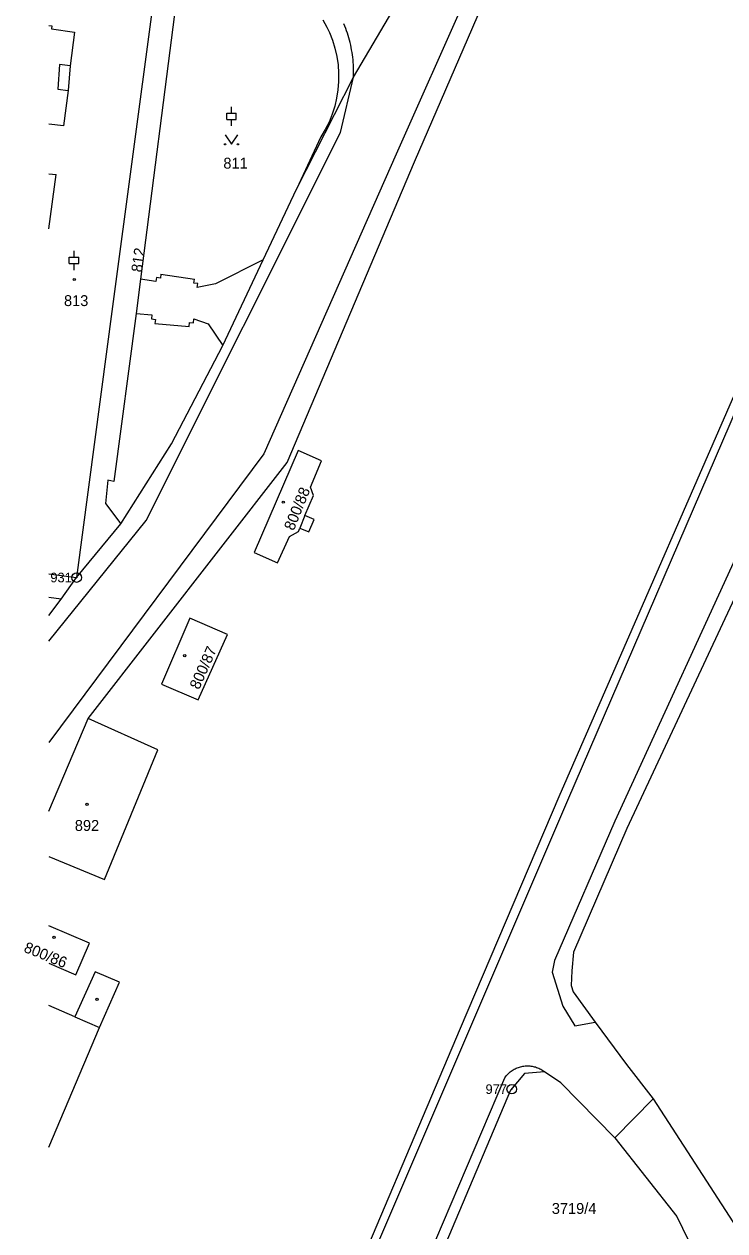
# Model space of a CAD drawing. Extents: x -747779 to -747197, y -965543 to -964919.
# Drawn here: x -747779.4 to -747670.1, y -965237.8 to -965049.6 of the extents above; entities that cross this region are included whole.
import ezdxf

# ---------------------------------------------------------------- set-up
doc = ezdxf.new("R2010")
doc.units = 0
for name, color, linetype in [('Hranice parcel', 7, 'Continuous'), ('Parcelní čísla', 7, 'Continuous'), ('Vnitřní kresba', 7, 'Continuous'), ('Značky bodu BP', 7, 'Continuous'), ('Značky budov', 7, 'Continuous'), ('Značky kultur', 7, 'Continuous')]:
    doc.layers.add(name, color=color, linetype=linetype)

msp = doc.modelspace()

# ---------------------------------------------------------------- linework, layer by layer
at = {"layer": 'Hranice parcel'}
for p, q in [((-747733.06, -965067.14), (-747736.89, -965075.33)), ((-747771.17, -965135.89), (-747764.28, -965127.51)), ((-747775.53, -965172.32), (-747769.38, -965157.87)), ((-747681.26, -965217.18), (-747687.21, -965223.29)), ((-747681.26, -965217.18), (-747664.09, -965243.73))]:
    msp.add_line(p, q, dxfattribs=at)
for points in [[(-747736.89, -965075.33), (-747728, -965057.84), (-747715.19, -965036.1), (-747687.81, -965009.8), (-747684.76, -965006.87), (-747683.74, -965004.84), (-747681.46, -965000.29)], [(-747769.38, -965157.87), (-747738.35, -965117.94), (-747718.46, -965071.07), (-747704.48, -965038.72), (-747704.11, -965038.88), (-747702.83, -965035.74), (-747698.69, -965025.95), (-747696.3, -965025.06), (-747693.83, -965026.45), (-747689.32, -965018.57), (-747684.62, -965015.84), (-747684.96, -965015.71), (-747684.72, -965015.07), (-747684.2, -965013.72), (-747680.21, -965004.33), (-747679.47, -965002.51), (-747679.51, -965002.12)], [(-747755.52, -965039.54), (-747756.37, -965045.62), (-747755.64, -965045.97), (-747761.21, -965089.37), (-747761.89, -965094.71), (-747765.38, -965120.93), (-747766.32, -965120.72), (-747766.67, -965124.36), (-747764.28, -965127.51)], [(-747759.34, -965046.86), (-747765.55, -965093.63), (-747771.17, -965135.89)], [(-747732.78, -965048.89), (-747732.14, -965050.03), (-747731.75, -965050.86), (-747731.27, -965052.08), (-747730.88, -965053.33), (-747730.58, -965054.6), (-747730.39, -965055.9), (-747730.3, -965057.2), (-747730.3, -965058.51), (-747730.41, -965059.82), (-747730.61, -965061.11), (-747730.91, -965062.39), (-747731.31, -965063.63), (-747731.8, -965064.84), (-747732.39, -965066.02), (-747733.06, -965067.14)], [(-747656.73, -965070.94), (-747661.79, -965091.8), (-747695.94, -965170.11), (-747711.36, -965206.23), (-747731.59, -965253.94)], [(-747764.28, -965127.51), (-747756.35, -965115.01), (-747748.36, -965099.71), (-747742.09, -965086.33), (-747736.89, -965075.33)], [(-747638.82, -965075.9), (-747639.42, -965076.84), (-747685.36, -965175.02), (-747693.65, -965194.31), (-747693.94, -965197.22), (-747694.04, -965199.52), (-747693.72, -965200.53), (-747690.27, -965205.24), (-747685.4, -965211.83), (-747681.26, -965217.18)], [(-747737.97, -965129.47), (-747736.58, -965128.7), (-747736.36, -965128.18), (-747734.96, -965128.78), (-747734.1, -965126.85), (-747735.55, -965126.22), (-747734.24, -965123.07), (-747734.71, -965121.78), (-747732.96, -965117.67), (-747736.63, -965116.06), (-747743.49, -965132), (-747739.82, -965133.61), (-747737.97, -965129.47)], [(-747775.53, -965135.31), (-747771.17, -965135.89)], [(-747775.53, -965141.81), (-747773.59, -965139.28), (-747771.17, -965135.89)], [(-747747.66, -965144.77), (-747753.49, -965142.24), (-747757.94, -965152.5), (-747752.19, -965154.98), (-747747.66, -965144.77)], [(-747775.53, -965179.42), (-747766.8, -965183), (-747758.5, -965162.75), (-747769.38, -965157.87)], [(-747775.53, -965196.03), (-747771.29, -965197.86), (-747769.14, -965192.93), (-747775.53, -965190.21)], [(-747775.53, -965224.76), (-747767.62, -965206.07), (-747764.49, -965199.02), (-747768.28, -965197.41), (-747771.44, -965204.42), (-747775.53, -965202.65)], [(-747687.21, -965223.29), (-747695.62, -965214.69), (-747698.17, -965212.99), (-747701.29, -965213.25), (-747703.51, -965215.83), (-747730.8, -965280.44), (-747731.85, -965282.88)], [(-747687.21, -965223.29), (-747677.55, -965235.57), (-747674.82, -965241.09), (-747670.12, -965258.53)]]:
    msp.add_lwpolyline(points, dxfattribs=at)
at = {"layer": 'Vnitřní kresba'}
for p, q in [((-747705.09, -965033.38), (-747721.35, -965069.83)), ((-747775.53, -965049.78), (-747775.04, -965049.86)), ((-747775.04, -965049.86), (-747775.11, -965050.3)), ((-747775.11, -965050.3), (-747771.49, -965050.84)), ((-747771.49, -965050.84), (-747772.18, -965056.08)), ((-747773.82, -965055.87), (-747774.12, -965059.7)), ((-747772.18, -965056.08), (-747773.82, -965055.87)), ((-747772.18, -965056.08), (-747772.51, -965059.91)), ((-747729.99, -965066.46), (-747728, -965057.84)), ((-747774.12, -965059.7), (-747772.51, -965059.91)), ((-747772.51, -965059.91), (-747773.23, -965065.46)), ((-747773.23, -965065.46), (-747775.53, -965065.18)), ((-747760.34, -965126.97), (-747729.99, -965066.46)), ((-747721.35, -965069.83), (-747741.97, -965116.6)), ((-747775.53, -965072.92), (-747774.38, -965073.05)), ((-747775.53, -965081.5), (-747774.38, -965073.05)), ((-747643.7, -965078.9), (-747687.21, -965173.91)), ((-747742.09, -965086.33), (-747749.51, -965090.09)), ((-747758.82, -965089.72), (-747761.21, -965089.37)), ((-747758.73, -965089.11), (-747758.82, -965089.72)), ((-747758.11, -965089.2), (-747758.73, -965089.11)), ((-747758.02, -965088.58), (-747758.11, -965089.2)), ((-747758.02, -965088.58), (-747752.79, -965089.34)), ((-747752.88, -965089.96), (-747752.79, -965089.34)), ((-747752.26, -965090.05), (-747752.88, -965089.96)), ((-747752.35, -965090.66), (-747752.26, -965090.05)), ((-747749.51, -965090.09), (-747752.35, -965090.66)), ((-747660.59, -965091.74), (-747694.6, -965170.66)), ((-747761.89, -965094.71), (-747759.46, -965094.93)), ((-747759.46, -965094.93), (-747759.51, -965095.56)), ((-747759.51, -965095.56), (-747758.89, -965095.62)), ((-747758.89, -965095.62), (-747758.95, -965096.24)), ((-747758.95, -965096.24), (-747753.63, -965096.73)), ((-747753.63, -965096.73), (-747753.57, -965096.11)), ((-747753.57, -965096.11), (-747752.95, -965096.17)), ((-747752.95, -965096.17), (-747752.89, -965095.54)), ((-747752.89, -965095.54), (-747750.66, -965096.31)), ((-747750.66, -965096.31), (-747748.36, -965099.71)), ((-747741.97, -965116.6), (-747775.53, -965161.63)), ((-747775.53, -965145.83), (-747760.34, -965126.97)), ((-747735.55, -965126.22), (-747736.36, -965128.18)), ((-747773.59, -965139.28), (-747775.53, -965139)), ((-747694.6, -965170.66), (-747730.5, -965254.41)), ((-747687.21, -965173.91), (-747696.62, -965195.61)), ((-747696.62, -965195.61), (-747697, -965197.45)), ((-747697, -965197.45), (-747695.33, -965202.76)), ((-747771.44, -965204.42), (-747767.62, -965206.07)), ((-747695.33, -965202.76), (-747693.45, -965205.83)), ((-747693.45, -965205.83), (-747690.27, -965205.24)), ((-747731.13, -965276.6), (-747704.39, -965213.92))]:
    msp.add_line(p, q, dxfattribs=at)
for points in [[(-747728, -965057.84), (-747727.98, -965057.45), (-747727.98, -965057.07), (-747727.98, -965056.68), (-747727.99, -965056.29), (-747728, -965055.9), (-747728.03, -965055.52), (-747728.06, -965055.13), (-747728.1, -965054.75), (-747728.15, -965054.36), (-747728.2, -965053.98), (-747728.27, -965053.6), (-747728.34, -965053.22), (-747728.42, -965052.84), (-747728.51, -965052.46), (-747728.6, -965052.08), (-747728.71, -965051.71), (-747728.82, -965051.34), (-747728.94, -965050.97), (-747729.06, -965050.6), (-747729.19, -965050.24), (-747729.33, -965049.88), (-747729.48, -965049.52)], [(-747704.39, -965213.92), (-747704.29, -965213.77), (-747704.17, -965213.63), (-747704.06, -965213.49), (-747703.93, -965213.36), (-747703.81, -965213.23), (-747703.67, -965213.11), (-747703.53, -965212.99), (-747703.39, -965212.88), (-747703.24, -965212.78), (-747703.09, -965212.68), (-747702.93, -965212.59), (-747702.77, -965212.51), (-747702.61, -965212.43), (-747702.44, -965212.36), (-747702.27, -965212.29), (-747702.1, -965212.24), (-747701.93, -965212.19), (-747701.75, -965212.15), (-747701.57, -965212.11), (-747701.39, -965212.08), (-747701.21, -965212.07), (-747701.03, -965212.05), (-747700.85, -965212.05), (-747700.67, -965212.05), (-747700.49, -965212.06), (-747700.31, -965212.08), (-747700.13, -965212.11), (-747699.95, -965212.14), (-747699.78, -965212.19), (-747699.6, -965212.23), (-747699.43, -965212.29), (-747699.26, -965212.35), (-747699.09, -965212.43), (-747698.93, -965212.5), (-747698.77, -965212.59), (-747698.61, -965212.68), (-747698.46, -965212.78), (-747698.31, -965212.88), (-747698.17, -965212.99)]]:
    msp.add_lwpolyline(points, dxfattribs=at)
at = {"layer": 'Značky bodu BP'}
for centre, radius in [((-747771.17, -965135.89), 0.75), ((-747771.17, -965135.89), 0.03), ((-747703.29, -965215.69), 0.75), ((-747703.29, -965215.69), 0.03)]:
    msp.add_circle(centre, radius, dxfattribs=at)
at = {"layer": 'Značky budov'}
for centre in [(-747771.53, -965089.4), (-747738.93, -965124.13), (-747754.3, -965148.07), (-747769.55, -965171.26), (-747774.69, -965192), (-747767.99, -965201.67)]:
    msp.add_circle(centre, 0.175, dxfattribs=at)
at = {"layer": 'Značky kultur'}
for p, q in [((-747747.01, -965063.45), (-747747.01, -965062.45)), ((-747747.76, -965063.45), (-747746.26, -965063.45)), ((-747747.76, -965064.45), (-747747.76, -965063.45)), ((-747747.76, -965064.45), (-747746.26, -965064.45)), ((-747747.01, -965065.45), (-747747.01, -965064.45)), ((-747746.26, -965064.45), (-747746.26, -965063.45)), ((-747772.33, -965085.93), (-747770.83, -965085.93)), ((-747772.33, -965086.93), (-747772.33, -965085.93)), ((-747771.58, -965085.93), (-747771.58, -965084.93)), ((-747770.83, -965086.93), (-747770.83, -965085.93)), ((-747772.33, -965086.93), (-747770.83, -965086.93)), ((-747771.58, -965087.93), (-747771.58, -965086.93))]:
    msp.add_line(p, q, dxfattribs=at)
msp.add_lwpolyline([(-747748.01, -965066.82), (-747747.01, -965068.32), (-747746.01, -965066.82)], dxfattribs=at)
for centre in [(-747748.01, -965068.32), (-747746.01, -965068.32)]:
    msp.add_circle(centre, 0.1, dxfattribs=at)

# ---------------------------------------------------------------- texts
at = {"layer": 'Parcelní čísla'}
for s, p in [('811', (-747748.28, -965072.11)), ('813', (-747773.14, -965093.55)), ('892', (-747771.45, -965175.41)), ('3719/4', (-747697.05, -965235.15))]:
    msp.add_text(s, height=1.7, dxfattribs=at).set_placement(p)
for s, rotation, p in [('812', 82, (-747760.99, -965088.35)), ('800/88', 68, (-747737.31, -965128.68)), ('800/87', 66, (-747752.07, -965153.47)), ('800/86', 338, (-747779.54, -965194.23))]:
    msp.add_text(s, height=1.7, rotation=rotation, dxfattribs=at).set_placement(p)
at = {"layer": 'Značky bodu BP'}
for s, p in [('931', (-747775.27, -965136.64)), ('977', (-747707.39, -965216.44))]:
    msp.add_text(s, height=1.5, dxfattribs=at).set_placement(p)

doc.saveas('drawing.dxf')
